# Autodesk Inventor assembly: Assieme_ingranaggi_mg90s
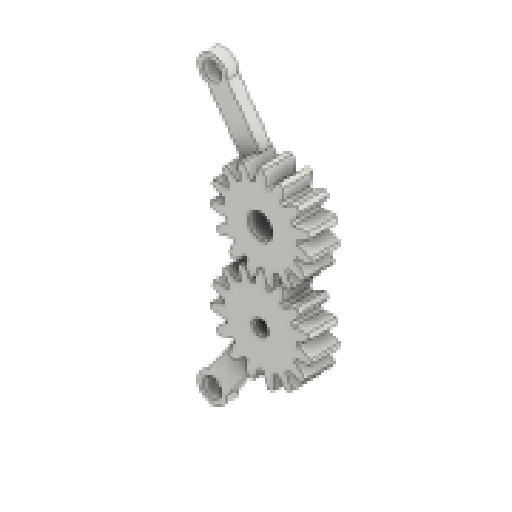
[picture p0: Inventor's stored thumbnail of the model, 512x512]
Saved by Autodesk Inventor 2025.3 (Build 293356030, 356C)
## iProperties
Created: 2026-03
Part Number: Assieme_ingranaggi_mg90s
Document SubType Name: Assembly
Designer: R5800u
Author: R5800u
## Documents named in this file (2)
- C:\Users\R5800u\Desktop\robot mg90s\Assieme_ingranaggi_mg90s.iam
- C:\Users\R5800u\Desktop\robot mg90s\Assieme_ingranaggi_mg90s\Design Accelerator\Ingranaggi cilindrici2.iam
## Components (1 placed, 1 different names)
1. Ingranaggi cilindrici:1 [sub-assembly]
